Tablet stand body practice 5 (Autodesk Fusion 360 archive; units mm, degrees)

design "mm-Tablet stand body practice 5" references "haas minimill"
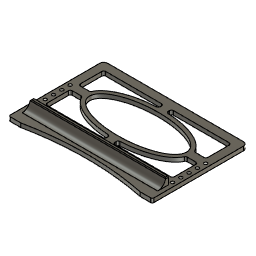
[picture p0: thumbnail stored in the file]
sketch "Sketch1" plane through (0, 0, 0) normal (0, 0, 1) x axis (1, 0, 0)
  line L1 (225.425, 0) -> (0, 0)
  line L2 (225.425, 149.225) -> (225.425, 0)
  line L3 (0, 149.225) -> (225.425, 149.225)
  line L4 (0, 0) -> (0, 149.225)
  point P1 (0, 0)
  point P2 (0, 0)
  point P3 (225.425, 0)
  point P5 (0, 149.225)
  horizontal L1
  vertical L2
  horizontal L3
  vertical L4
  coincident P1 P2
  dimension "d1" distance P2 P3 = 225.425
  dimension "d2" distance P2 P5 = 149.225
extrude "Extrude1" new body sketch "Sketch1" along normal blind 6.35
sketch "Sketch2" plane through (225.425, 0, 0) normal (1, 0, 0) x axis (0, 1, 0)
  line L1 (149.225, 0) -> (0, 0)
  line L2 (149.225, 6.35) -> (149.225, 0)
  line L3 (0, 6.35) -> (149.225, 6.35)
  line L4 (0, 0) -> (0, 6.35)
  line L5 (15.875, 6.35) -> (0, 6.35)
  line L6 (28.575, 6.35) -> (15.875, 6.35)
  line L7 (28.575, 17.907) -> (28.575, 6.35)
  line L8 (31.75, 17.907) -> (28.575, 17.907)
  line L9 (31.75, 6.35) -> (31.75, 17.907)
  line L10 (28.575, 6.35) -> (31.75, 6.35)
  line L11 (27.305, 6.35) -> (28.575, 6.35)
  line L12 (27.305, 16.637) -> (27.305, 6.35)
  line L13 (27.305, 16.637) -> (28.575, 17.907)
  line L14 (34.0111, 17.907) -> (28.575, 17.907)
  point P5 (0, 6.35)
  point P6 (0, 6.35)
  point P11 (31.75, 6.35)
  point P7 (15.875, 6.35)
  point P8 (28.575, 6.35)
  point P9 (28.575, 17.907)
  point P10 (31.75, 17.907)
  point P12 (27.305, 6.35)
  coincident P5 P6
  perpendicular L4 L5
  parallel L3 L6
  perpendicular L6 L7
  perpendicular L7 L8
  coincident L3 P11
  perpendicular L3 L9
  perpendicular L7 L11
  perpendicular L6 L12
  horizontal L14
  dimension "d5" distance P6 P7 = 15.875
  dimension "d6" distance P7 P8 = 12.7
  dimension "d8" distance P8 P9 = 11.557
  dimension "d9" distance P9 P10 = 3.175
  dimension "d10" distance P8 P12 = 1.27
  dimension "d11" angle L13 L14 = 135
extrude "Extrude2" add sketch "Sketch2" profile of L3 L6 L7 L8 L9 L10 L11 L12 L13 against normal blind 225.425
fillet "Fillet1" radius 12.7
sketch "Sketch3" plane through (0, 0, 6.35) normal (0, 0, 1) x axis (-1, 0, 0)
  line L1 (0, -14.8363) -> (-225.425, -14.8363)
  line L2 (0, 0) -> (0, -14.8363)
  line L3 (-225.425, 0) -> (0, 0)
  line L4 (-225.425, -14.8363) -> (-225.425, 0)
  line L5 (-19.05, 0) -> (0, 0)
  line L6 (-206.375, 0) -> (-225.425, 0)
  line L7 (-206.375, 0) -> (-19.05, 0)
  arc A1 centre (-112.7125, 457.2) radius 466.6953 clockwise from (-19.05, 0) to (-206.375, 0)
  point P4 (0, 0)
  point P6 (0, 0)
  point P5 (-225.425, 0)
  point P8 (-225.425, 0)
  point P7 (-19.05, 0)
  point P9 (-206.375, 0)
  point P10 (-112.7125, 457.2)
  coincident P4 P6
  perpendicular L2 L5
  coincident P5 P8
  perpendicular L4 L6
  dimension "d16" distance P6 P7 = 19.05
  dimension "d17" distance P8 P9 = 19.05
  dimension "d18" distance L3 P10 = 457.2
extrude "Extrude3" cut sketch "Sketch3" profile of L3 A1 L7 against normal blind 6.35
sketch "Sketch4" plane through (0, 0, 17.907) normal (0, 0, 1) x axis (-1, 0, 0)
  line L1 (-225.425, -31.75) -> (-225.425, -28.575)
  line L2 (0, -31.75) -> (-225.425, -31.75)
  line L3 (0, -28.575) -> (0, -31.75)
  line L4 (-225.425, -28.575) -> (0, -28.575)
  line L5 (-6.35, -31.75) -> (0, -31.75)
  line L6 (-6.35, -12.7) -> (-6.35, -31.75)
  line L7 (0, -12.7) -> (-6.35, -12.7)
  line L8 (0, -31.75) -> (0, -12.7)
  point P4 (0, -31.75)
  point P6 (0, -31.75)
  point P7 (-6.35, -31.75)
  point P9 (0, -12.7)
  horizontal L5
  vertical L6
  horizontal L7
  vertical L8
  coincident P4 P6
  dimension "d21" distance P6 P7 = 6.35
  dimension "d22" distance P6 P9 = 19.05
work_plane "WorkPlane1"
extrude "Extrude4" cut sketch "Sketch4" profile of L2 L3 L4 L5 L6 L7 L8 to an object
sketch "Sketch5" plane through (0, 0, 17.907) normal (0, 0, 1) x axis (-1, 0, 0)
  line L1 (-6.35, -28.575) -> (-6.35, -31.75)
  line L2 (-225.425, -28.575) -> (-6.35, -28.575)
  line L3 (-225.425, -31.75) -> (-225.425, -28.575)
  line L4 (-6.35, -31.75) -> (-225.425, -31.75)
  line L5 (-219.075, -31.75) -> (-225.425, -31.75)
  line L6 (-219.075, -12.7) -> (-219.075, -31.75)
  line L7 (-225.425, -12.7) -> (-219.075, -12.7)
  line L8 (-225.425, -31.75) -> (-225.425, -12.7)
  point P5 (-225.425, -31.75)
  point P6 (-225.425, -31.75)
  point P7 (-219.075, -31.75)
  point P9 (-225.425, -12.7)
  horizontal L5
  vertical L6
  horizontal L7
  vertical L8
  coincident P5 P6
  dimension "d25" distance P6 P7 = 6.35
  dimension "d26" distance P6 P9 = 19.05
extrude "Extrude5" cut sketch "Sketch5" profile of L2 L3 L4 L5 L6 L7 L8 to an object
chamfer "Chamfer1" distance 1.27
sketch "Sketch6" plane through (0, 0, 6.35) normal (0, 0, 1) x axis (-1, 0, 0)
  line L1 (-225.425, -149.225) -> (-225.425, 0)
  line L2 (0, -149.225) -> (-225.425, -149.225)
  line L3 (0, 0) -> (0, -149.225)
  line L4 (-19.05, 0) -> (0, 0)
  line L5 (-225.425, 0) -> (-206.375, 0)
  line L6 (-219.075, -14.8363) -> (-219.075, -31.75)
  line L7 (-6.35, -14.8363) -> (-219.075, -14.8363)
  line L8 (-6.35, -31.75) -> (-6.35, -14.8363)
  line L9 (-219.075, -31.75) -> (-6.35, -31.75)
  line L10 (-112.7125, -31.75) -> (-112.7125, -149.225)
  line L11 (-225.425, -90.4875) -> (-112.7125, -90.4875)
  curve K1 (-188.9125, -90.4875) -> (-36.5125, -90.4875)
  curve K2 (-112.7125, -122.2375) -> (-112.7125, -58.7375)
  arc A1 centre (-112.7125, 457.2) radius 466.6953 clockwise from (-19.05, 0) to (-206.375, 0)
  closed curve K3 centre (-112.7125, -90.4875)
  point P13 (-112.7125, -149.225)
  point P14 (-112.7125, -31.75)
  point P15 (-112.7125, -90.4875)
  point P18 (-36.5125, -90.4875)
  point P19 (-188.9125, -90.4875)
  point P20 (-112.7125, -58.7375)
  point P21 (-112.7125, -122.2375)
  point P17 (-112.7125, -90.4875)
  point P16 (-225.425, -90.4875)
  midpoint L2 P13
  midpoint L9 P14
  midpoint L10 P15
  perpendicular L10 L11
  coincident K3 P18
  coincident K3 P19
  coincident K3 P20
  coincident K3 P21
  coincident P15 P17
  perpendicular L10 K1
  coincident L1 P16
  dimension "d37" distance K3 = 152.4
  dimension "d38" = 31.75
extrude "Extrude6" cut sketch "Sketch6" profile of L10 L11 K3 no distance stored
sketch "Sketch7" plane through (0, 0, 6.35) normal (0, 0, 1) x axis (-1, 0, 0)
  line L1 (-212.725, -136.525) -> (-12.7, -136.525)
  line L2 (-212.725, -44.45) -> (-212.725, -136.525)
  line L3 (-12.7, -44.45) -> (-212.725, -44.45)
  line L4 (-12.7, -136.525) -> (-12.7, -44.45)
  line L5 (-225.425, -149.225) -> (-225.425, 0)
  line L6 (0, -149.225) -> (-225.425, -149.225)
  line L7 (0, 0) -> (0, -149.225)
  line L8 (-19.05, 0) -> (0, 0)
  line L9 (-225.425, 0) -> (-206.375, 0)
  line L10 (-219.075, -14.8363) -> (-219.075, -31.75)
  line L11 (-6.35, -14.8363) -> (-219.075, -14.8363)
  line L12 (-6.35, -31.75) -> (-6.35, -14.8363)
  line L13 (-219.075, -31.75) -> (-6.35, -31.75)
  line L14 (-106.3625, -90.4875) -> (-112.7125, -90.4875)
  line L15 (-112.7125, -44.45) -> (-112.7125, -90.4875)
  line L16 (-112.7125, -136.525) -> (-112.7125, -90.4875)
  line L17 (-106.3625, -84.1375) -> (-106.3625, -90.4875)
  line L18 (-106.3625, -44.45) -> (-106.3625, -52.5004)
  line L19 (-119.0625, -84.1375) -> (-119.0625, -90.4875)
  line L20 (-119.0625, -44.45) -> (-119.0625, -52.5004)
  line L21 (-106.3625, -122.1271) -> (-106.3625, -90.4875)
  line L22 (-106.3625, -136.525) -> (-106.3625, -128.4746)
  line L23 (-119.0625, -122.1271) -> (-119.0625, -90.4875)
  line L24 (-119.0625, -136.525) -> (-119.0625, -128.4746)
  line L25 (-119.0625, -84.1375) -> (-112.7125, -84.1375)
  line L26 (-212.725, -84.1375) -> (-194.1079, -84.1375)
  line L27 (-119.0625, -96.8375) -> (-112.7125, -96.8375)
  line L28 (-212.725, -96.8375) -> (-194.1079, -96.8375)
  line L29 (-119.0625, -90.4875) -> (-112.7125, -90.4875)
  line L30 (-195.2625, -90.4875) -> (-188.9125, -90.4875)
  line L31 (-38.0521, -84.1375) -> (-112.7125, -84.1375)
  line L32 (-12.7, -84.1375) -> (-31.3171, -84.1375)
  line L33 (-38.0521, -96.8375) -> (-112.7125, -96.8375)
  line L34 (-12.7, -96.8375) -> (-31.3171, -96.8375)
  closed curve K1 centre (-112.7125, -90.4875)
  arc A1 centre (-112.7125, 457.2) radius 466.6953 clockwise from (-19.05, 0) to (-206.375, 0)
  closed curve K2 centre (-112.7125, -90.4875)
  closed curve K3 centre (-112.7125, -90.4875)
  point P6 (-112.7125, -90.4875)
  point P20 (-112.7125, -90.4875)
  point P18 (-112.7125, -90.4875)
  point P21 (-112.7125, -90.4875)
  point P22 (-112.7125, -44.45)
  point P23 (-112.7125, -90.4875)
  point P24 (-112.7125, -136.525)
  point P39 (-106.3625, -84.1375)
  point P41 (-119.0625, -52.5004)
  point P42 (-106.3625, -52.5004)
  point P43 (-106.3625, -122.1271)
  point P44 (-106.3625, -128.4746)
  point P45 (-119.0625, -122.1271)
  point P46 (-119.0625, -128.4746)
  point P47 (-119.0625, -96.8375)
  point P48 (-194.1079, -96.8375)
  point P49 (-194.1079, -84.1375)
  point P50 (-188.9125, -90.4875)
  point P51 (-195.2625, -90.4875)
  point P52 (-38.0521, -84.1375)
  point P53 (-31.3171, -84.1375)
  point P54 (-38.0521, -96.8375)
  point P55 (-31.3171, -96.8375)
  horizontal L1
  vertical L2
  horizontal L3
  vertical L4
  coincident P6 P20
  perpendicular L2 L29
  coincident P18 P21
  midpoint L3 P22
  perpendicular L3 L15
  coincident P18 P23
  midpoint L1 P24
  coincident P39 L31
  collinear L17 L18
  collinear L19 L20
  coincident K3 P41
  coincident K3 P42
  coincident K1 P43
  coincident K3 P44
  collinear L21 L22
  coincident K1 P45
  coincident K3 P46
  collinear L23 L24
  collinear L25 L26
  coincident L23 P47
  collinear L27 L28
  coincident K3 P48
  coincident K3 P49
  coincident K1 P50
  collinear L29 L30
  coincident K3 P51
  coincident K1 P52
  coincident K3 P53
  collinear L31 L32
  coincident K1 P54
  coincident K3 P55
  collinear L33 L34
  dimension "d65" distance L1 L6 = 12.7
  dimension "d66" distance L2 L5 = 12.7 (= "d65")
  dimension "d67" distance L3 L13 = 12.7
  dimension "d68" = 38.1
extrude "Extrude7" cut sketch "Sketch7" profile of L1 L2 L3 L4 K3 L24 L22 L26 L32 L28 L34 L18 L20 no distance stored
fillet "Fillet2" radius 3
fillet "Fillet3" radius 3
hole "Hole1" HoleDepth 35.56 HoleDiameter 5.035 TipAngle 118 RefDim1 6.35 RefDim2 38.1
rectangular_pattern "R-Pattern1" uSpaceDistance -52.07 vSpaceDistance 212.725
fillet "Fillet4" radius 6
fillet "Fillet5" radius 2.5
fillet "Fillet6" radius 2.5
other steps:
thread "Thread1"

design "haas minimill"
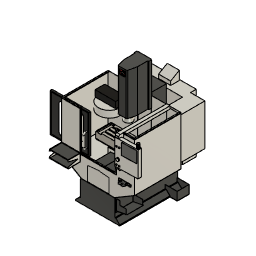
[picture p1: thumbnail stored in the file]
